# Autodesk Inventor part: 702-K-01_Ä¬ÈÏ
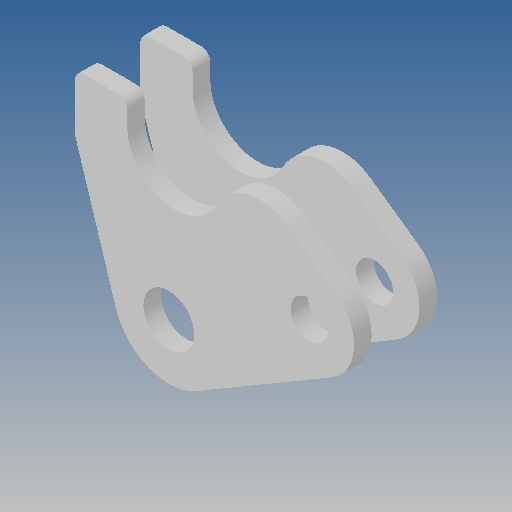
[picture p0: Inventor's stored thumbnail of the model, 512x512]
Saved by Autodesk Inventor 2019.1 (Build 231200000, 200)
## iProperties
Created: 2010-06
Part Number: 702-K-01_Ä¬ÈÏ
Material: Ogólny
Document SubType Name: Modeling
Designer: CADENGINEERING4
Density: 1 g/cm^3
Appearance: Domyślna
Author: CADENGINEERING4
Revision Number: ÈÎºÎ
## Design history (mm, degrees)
feature "NONE"
feature "NONE:1"
node "Bryła1"
node "Bryła2"
